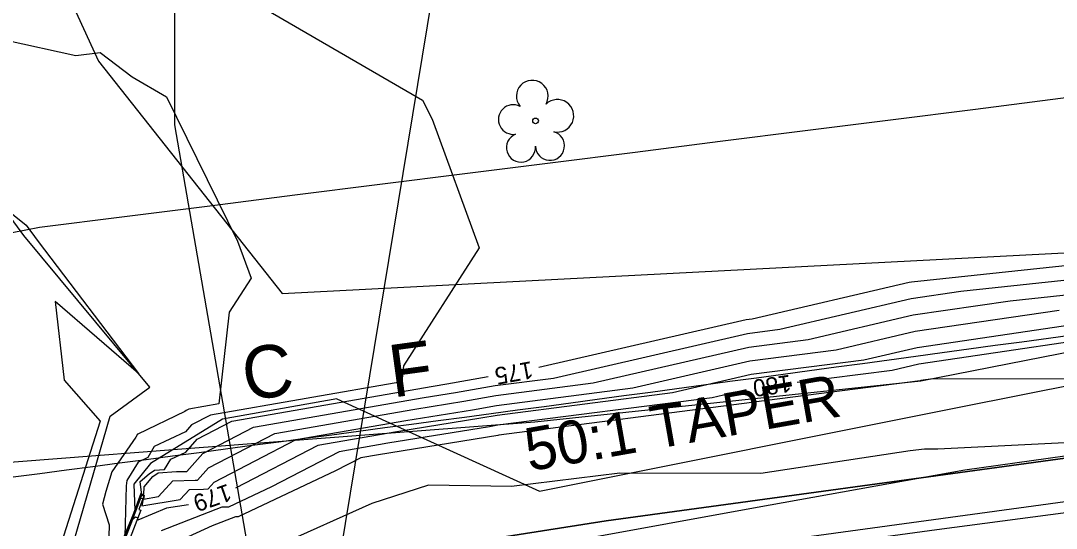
# Model space of a CAD drawing. Extents: x 2086416 to 2115205, y 575507 to 632762.
# Drawn here: x 2111556.7 to 2111677.4, y 581680.1 to 581739.2 of the extents above; entities that cross this region are included whole.
import ezdxf

# ---------------------------------------------------------------- set-up
doc = ezdxf.new("R2010")
doc.units = 0
for name, color, linetype in [('Default', 7, 'Continuous'), ('DTM Contours Major', 7, 'Continuous'), ('DTM Contours Major Text', 7, 'Continuous'), ('DTM Contours Minor', 7, 'Continuous'), ('DTM Contours Minor Text', 7, 'Continuous'), ('Exist Guardrail', 7, 'Continuous'), ('Exist Hydro Stream or Body of Water', 7, 'Continuous'), ('Exist Hydrographic FEMA Cross Section', 7, 'Continuous'), ('Exist Hydrographic Stream Bed', 7, 'Continuous'), ('Exist Right of Way Line', 7, 'Continuous'), ('Exist Roads EOP', 7, 'Continuous'), ('Exist Structure Major Bridge WW', 7, 'Continuous'), ('Exist Vegetation Tree CELL', 7, 'Continuous'), ('Exist Vegetation Woods Line', 7, 'Continuous'), ('Prop Horizontal Alignment Station Label', 7, 'Continuous'), ('Prop SS Cut Line', 7, 'Continuous'), ('Prop SS Cut Text', 7, 'Continuous'), ('Prop SS Fill Line', 7, 'Continuous'), ('Prop SS Fill Text', 7, 'Continuous')]:
    doc.layers.add(name, color=color, linetype=linetype)

# ---------------------------------------------------------------- blocks, each defined once
blk = doc.blocks.new('EXIST VEGETATION TREE')
at = {"layer": 'Exist Vegetation Tree CELL'}
blk.add_line((0, 0), (0, 0), dxfattribs=at)
blk.add_circle((0, 0), 0.00652, dxfattribs=at)
for centre, radius, start, end in [((-0.0077, 0.0575), 0.0371, 330.1651, 219.7134), ((0.051, 0.0118), 0.038, 257.1011, 134.1999), ((-0.0521, 0.0031), 0.0345, 62.6636, 279.3457), ((-0.0341, -0.0624), 0.0338, 111.5671, 6.231), ((0.0335, -0.058), 0.034, 181.2822, 74.56)]:
    blk.add_arc(centre, radius, start, end, dxfattribs=at)

msp = doc.modelspace()

# ---------------------------------------------------------------- linework, layer by layer
at = {"layer": 'Default'}
for p, q in [((2111430.06, 581649.33), (2112312.03, 581769.69)), ((2111624.94, 581680.97), (2111995.53, 581731.54)), ((2111995.53, 581731.54), (2111624.94, 581680.97)), ((2111596.11, 581676.45), (2111624.94, 581680.97)), ((2111624.94, 581680.97), (2111596.11, 581676.45))]:
    msp.add_line(p, q, dxfattribs=at)
at = {"layer": 'DTM Contours Major'}
for points in [[(2111617.1, 581698.85), (2111641.26, 581704.4), (2111641.96, 581704.49), (2111660.29, 581708.76), (2111660.56, 581708.8), (2111690.12, 581711.96), (2111707.48, 581713.81), (2111708.18, 581713.93), (2111715.64, 581714.84)], [(2111746.21, 581711.02), (2111744.42, 581710.79), (2111740.33, 581710.21), (2111740.15, 581710.16), (2111739.89, 581710.15), (2111710.46, 581706), (2111704.42, 581705.57), (2111692.08, 581703.63), (2111691.03, 581703.52), (2111689.24, 581703.33), (2111661.42, 581699.22), (2111658.28, 581698.49), (2111647.23, 581697.07)], [(2111568.39, 581677.72), (2111570.78, 581684.17), (2111570.79, 581684.17), (2111570.79, 581684.25), (2111570.65, 581685.53), (2111571.69, 581686.42), (2111572.31, 581686.85), (2111573.5, 581686.94), (2111574.21, 581688.15), (2111575.95, 581688.97), (2111577.3, 581690.48), (2111581.33, 581692.57), (2111604.78, 581696.65), (2111606.4, 581696.91), (2111611.21, 581697.76)], [(2111641.29, 581696.23), (2111637.3, 581695.31), (2111612.35, 581692.09), (2111611.36, 581691.91), (2111599.5, 581689.99), (2111593.85, 581689.01), (2111585.96, 581684.92), (2111580.95, 581682.57), (2111580.17, 581682.56), (2111573.08, 581679.8)]]:
    msp.add_lwpolyline(points, dxfattribs=at)
at = {"layer": 'DTM Contours Minor'}
for points in [[(2111582.17, 581742.39), (2111603.57, 581729.99), (2111604.67, 581727.75), (2111610.14, 581712.75), (2111601.35, 581699.02), (2111601.14, 581697.17), (2111578.83, 581693.28), (2111576.64, 581692.15), (2111575.91, 581691.33), (2111572.29, 581689.61), (2111571.53, 581688.32), (2111570.42, 581687.8), (2111569.11, 581685.65), (2111569.01, 581685.02), (2111568.86, 581679.13)], [(2111555.04, 581736.97), (2111563.15, 581735.16), (2111565.98, 581735.53), (2111569.71, 581732.7), (2111573.71, 581730.38), (2111581.99, 581713.56), (2111583.57, 581709.22), (2111581.03, 581705.26), (2111579.81, 581694.6), (2111576.33, 581693.99), (2111575.99, 581693.82), (2111575.87, 581693.69), (2111570.36, 581691.07), (2111570.35, 581691.05), (2111570.34, 581691.05), (2111570.14, 581690.71), (2111567.36, 581686.68), (2111566.66, 581684.37), (2111566.24, 581682.91), (2111567.02, 581680.5), (2111566.85, 581673.86)], [(2111554.56, 581717.65), (2111557.36, 581715.39), (2111558.77, 581713.51), (2111570.46, 581698.12), (2111560.75, 581706.53), (2111561.78, 581697.35), (2111565.99, 581692.59), (2111561.42, 581678.3), (2111560.17, 581674.93), (2111560.63, 581673.94), (2111560, 581669.27), (2111560.03, 581668.96), (2111560.71, 581660.16), (2111561.06, 581659.54), (2111561.4, 581658.89), (2111569.8, 581645.9), (2111570.55, 581641.09), (2111570.69, 581640.85), (2111570.83, 581641.04), (2111571.48, 581641.08), (2111571.48, 581641.08), (2111571.48, 581641.09), (2111571.57, 581640.98), (2111575.14, 581635.69)], [(2111778.53, 581716.52), (2111760.29, 581714.29), (2111743.84, 581712.22), (2111739.7, 581711.72), (2111714.98, 581708.61), (2111709.96, 581708), (2111695.16, 581705.67), (2111690.85, 581705.21), (2111683.5, 581704.42), (2111661.19, 581701.13), (2111655.01, 581699.69), (2111641.87, 581698), (2111632.68, 581695.88), (2111612.27, 581693.25), (2111610.37, 581692.91), (2111600.55, 581691.33), (2111591.35, 581689.72), (2111581.74, 581684.75)], [(2111569.26, 581679.92), (2111570.8, 581684.09), (2111571.06, 581684.04), (2111571.12, 581684.94), (2111572.14, 581686.13), (2111572.74, 581686.54), (2111574.87, 581686.7), (2111576.06, 581686.72), (2111576.08, 581686.72), (2111577.96, 581688.82), (2111583.84, 581691.86), (2111603.73, 581695.32), (2111607.39, 581695.91), (2111612.02, 581696.73), (2111618.81, 581697.6), (2111641.42, 581702.8), (2111645.22, 581703.29), (2111660.52, 581706.85), (2111666.29, 581707.71), (2111690.3, 581710.27)], [(2111771.48, 581708.94), (2111760.55, 581707.39), (2111751.32, 581706.07), (2111741.05, 581703.18), (2111726.36, 581703.03), (2111711.26, 581700.9), (2111699.31, 581700.06), (2111691.64, 581698.04), (2111679.98, 581697.46), (2111663.05, 581697.52), (2111661.64, 581697.31), (2111661.54, 581697.28), (2111642.18, 581694.8), (2111641.92, 581694.74), (2111612.43, 581690.93), (2111612.35, 581690.91), (2111598.44, 581688.66), (2111596.35, 581688.3), (2111593.43, 581686.79), (2111582.07, 581681.44), (2111581.77, 581681.43), (2111579.05, 581680.38), (2111575.31, 581678.67)], [(2111566.54, 581672.9), (2111570.12, 581682.11), (2111570.82, 581684.01), (2111571.02, 581683.97), (2111571.12, 581683.93), (2111571.04, 581683.49), (2111572.78, 581683.78), (2111574.45, 581685.63), (2111577.05, 581685.69), (2111577.33, 581685.71), (2111578.62, 581687.15), (2111586.34, 581691.15), (2111602.67, 581693.99), (2111608.38, 581694.91), (2111612.1, 581695.57), (2111623.43, 581697.03), (2111641.57, 581701.2), (2111648.49, 581702.09), (2111660.74, 581704.95), (2111672.03, 581706.61), (2111690.48, 581708.58)], [(2111566.55, 581672.89), (2111570.69, 581683.54), (2111570.77, 581683.6), (2111570.96, 581683.55), (2111571.01, 581683.53), (2111570.84, 581682.71), (2111575.32, 581683.44), (2111576.38, 581684.62), (2111578.04, 581684.65), (2111578.57, 581684.69), (2111579.28, 581685.48), (2111588.84, 581690.43), (2111601.61, 581692.66), (2111609.37, 581693.91), (2111612.19, 581694.41), (2111628.06, 581696.46), (2111641.72, 581699.6), (2111651.75, 581700.89), (2111660.97, 581703.04), (2111677.77, 581705.52)], [(2111775.95, 581702.18), (2111765.88, 581701.69), (2111760.91, 581700.98), (2111757.86, 581700.67), (2111741.95, 581696.21), (2111712.84, 581695.91), (2111712.06, 581695.8), (2111711.43, 581695.75), (2111692.47, 581690.75), (2111663.6, 581689.32), (2111662.08, 581689.32), (2111660.39, 581689.12), (2111642.99, 581686.48), (2111626.56, 581686.5), (2111613.94, 581684.95), (2111604.27, 581685.12), (2111597.65, 581682.97), (2111586.74, 581678.08), (2111579.19, 581676.52)], [(2111576.27, 581682.84), (2111573.71, 581682.42), (2111570.37, 581681.02), (2111570.38, 581681.33), (2111570.36, 581681.36), (2111570.32, 581681.3), (2111570.11, 581681.39), (2111569.76, 581681.12), (2111566.56, 581672.88), (2111566.54, 581672.9), (2111566.38, 581672.88), (2111566.24, 581672.86), (2111566.42, 581671.65), (2111567.12, 581666.77), (2111567.76, 581662.76), (2111570.69, 581642.93), (2111570.61, 581642.81), (2111570.86, 581641.18), (2111571.15, 581641.2), (2111571.31, 581641.22), (2111571.26, 581641.66)]]:
    msp.add_lwpolyline(points, dxfattribs=at)
at = {"layer": 'Exist Guardrail'}
msp.add_lwpolyline([(2111568.01, 581669.49), (2111592.86, 581673.51), (2111642.15, 581682.49), (2111666.78, 581686.92), (2111710.04, 581692.98), (2111759.58, 581699.83), (2111809.18, 581706.83), (2111858.62, 581713.63), (2111908.17, 581720.55), (2111932.9, 581724.16), (2111951.42, 581726.24), (2112007.61, 581731.07), (2112026.51, 581732.21), (2112051.9, 581735.26)], dxfattribs=at)
at = {"layer": 'Exist Hydro Stream or Body of Water'}
msp.add_lwpolyline([(2111621.04, 581592.2), (2111611.64, 581604.33), (2111605.91, 581608.14), (2111600.48, 581607.01), (2111602.12, 581600.1), (2111601.11, 581599.2), (2111587.78, 581617.38), (2111576.69, 581633.34), (2111571.48, 581641.08), (2111570.64, 581641.03), (2111569.87, 581645.92), (2111561.21, 581659.64), (2111560.4, 581669.08), (2111561.77, 581674.66), (2111567.14, 581693.15), (2111571.77, 581696.53), (2111557.1, 581714.2), (2111551.35, 581722.03)], dxfattribs=at)
at = {"layer": 'Exist Hydrographic FEMA Cross Section'}
msp.add_lwpolyline([(2111757.26, 581740.16), (2111747.34, 581738.91), (2111742.38, 581738.29), (2111737.42, 581737.66), (2111727.5, 581736.41), (2111717.58, 581735.16), (2111707.67, 581733.91), (2111697.75, 581732.65), (2111687.83, 581731.4), (2111677.92, 581730.15), (2111668, 581728.9), (2111658.08, 581727.65), (2111648.17, 581726.4), (2111638.25, 581725.14), (2111628.33, 581723.89), (2111618.42, 581722.64), (2111608.5, 581721.39), (2111598.58, 581720.14), (2111588.67, 581718.89), (2111578.75, 581717.64), (2111568.83, 581716.38), (2111558.92, 581715.13), (2111549.31, 581713.26)], dxfattribs=at)
at = {"layer": 'Exist Hydrographic Stream Bed'}
msp.add_lwpolyline([(2112129.65, 582477.71), (2111835.9, 582368.96), (2111727.15, 582231.15), (2111672.65, 582129.59), (2111610.9, 582009.96), (2111585.65, 581897.53), (2111574.65, 581806.9), (2111574.65, 581727.08), (2111582.9, 581679.52), (2111589.15, 581643.7), (2111621.9, 581589.33), (2111665.4, 581516.77), (2111701.65, 581379.01), (2111737.9, 581248.45), (2111785.15, 581103.39)], dxfattribs=at)
at = {"layer": 'Exist Right of Way Line'}
msp.add_arc((2108326.55, 606231.5), 24756.94, 277.393911, 277.856215, dxfattribs=at)
at = {"layer": 'Exist Roads EOP'}
msp.add_lwpolyline([(2111568.95, 581657.38), (2111567.48, 581667.28), (2111614.17, 581673.23), (2111663.5, 581679.94), (2111712.97, 581686.46), (2111762.01, 581693.34), (2111810.99, 581700.16), (2111860.08, 581706.99), (2111909.44, 581713.78), (2111958.29, 581720.29), (2112007.47, 581726.81), (2112052.56, 581733.02), (2112053.87, 581723.65)], dxfattribs=at)
msp.add_lwpolyline([(2111568.95, 581657.38), (2111567.48, 581667.28), (2111614.17, 581673.23), (2111663.5, 581679.94), (2111712.97, 581686.46), (2111762.01, 581693.34), (2111810.99, 581700.16), (2111860.08, 581706.99), (2111909.44, 581713.78), (2111958.29, 581720.29), (2112007.47, 581726.81), (2112052.56, 581733.02), (2112053.87, 581723.65)], dxfattribs=at)
at = {"layer": 'Exist Structure Major Bridge WW'}
msp.add_lwpolyline([(2111566.58, 581672.83), (2111566.85, 581673.52), (2111570.25, 581682.39), (2111570.84, 581683.94), (2111571.08, 581683.85), (2111570.48, 581682.3), (2111570.72, 581682.21), (2111567.32, 581673.34), (2111567.08, 581673.43), (2111566.66, 581672.32), (2111566.58, 581672.83)], dxfattribs=at)
at = {"layer": 'Exist Vegetation Woods Line'}
for points in [[(2111543, 581784.1), (2111565.77, 581734.52), (2111587.19, 581707.45), (2111708.99, 581713.78), (2111811.99, 581727.73), (2111909.41, 581740.4), (2112007.41, 581746.55), (2112041.96, 581749.79), (2112042.22, 581740.22)], [(2112042.22, 581740.22), (2112007.09, 581741.23), (2111957.14, 581737.86), (2111908.66, 581731.85), (2111808.65, 581718.24), (2111760.41, 581712.7), (2111710.34, 581706.77), (2111661.65, 581697.22), (2111616.66, 581692.44), (2111575, 581689.29), (2111546.91, 581687.08), (2111515.04, 581695.86), (2111502.17, 581702.85), (2111491.11, 581719.62), (2111479.28, 581746.11)]]:
    msp.add_lwpolyline(points, dxfattribs=at)
at = {"layer": 'Prop Horizontal Alignment Station Label'}
msp.add_line((2111591.21, 581660.22), (2111612.47, 581789.24), dxfattribs=at)
at = {"layer": 'Prop SS Cut Line'}
for p, q in [((2111593.56, 581695.16), (2111580.25, 581692.82)), ((2111580.25, 581692.82), (2111571.84, 581687.65)), ((2111571.84, 581687.65), (2111569.9, 581685.25)), ((2111569.9, 581685.25), (2111570.02, 581682.16)), ((2111570.02, 581682.16), (2111566.13, 581672.9))]:
    msp.add_line(p, q, dxfattribs=at)
at = {"layer": 'Prop SS Fill Line'}
for p, q in [((2111666.3, 581694.23), (2111715.42, 581704.07)), ((2111593.56, 581695.16), (2111617.18, 581684.41)), ((2111617.18, 581684.41), (2111666.3, 581694.23))]:
    msp.add_line(p, q, dxfattribs=at)

# ---------------------------------------------------------------- block references
at = {"layer": 'Exist Vegetation Tree CELL', "xscale": 50, "yscale": 50}
msp.add_blockref('EXIST VEGETATION TREE', (2111616.73, 581727.56), dxfattribs=at)

# ---------------------------------------------------------------- texts
at = {"layer": 'Default'}
msp.add_text('50:1 TAPER', height=5, rotation=9.9963, dxfattribs=at).set_placement((2111615.97, 581686.72))
at = {"layer": 'DTM Contours Major Text'}
for s, rotation, p in [('175', 190.4661, (2111616.23, 581699.57)), ('180', 188.0334, (2111646.37, 581697.99))]:
    msp.add_text(s, height=2, rotation=rotation, dxfattribs=at).set_placement(p)
at = {"layer": 'DTM Contours Minor Text'}
msp.add_text('179', height=2, rotation=199.2544, dxfattribs=at).set_placement((2111580.85, 581685.31))
at = {"layer": 'Prop SS Cut Text'}
msp.add_text('C', height=6.1, rotation=7.771, dxfattribs=at).set_placement((2111582.97, 581694.94))
at = {"layer": 'Prop SS Fill Text'}
msp.add_text('F', height=6.1, rotation=7.771, dxfattribs=at).set_placement((2111600.1, 581695.32))

doc.saveas('drawing.dxf')
